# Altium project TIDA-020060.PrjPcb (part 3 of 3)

## Sheet Automotive_PoDL_PSE_Adapter_Hardware.SchDoc
size 431 x 279 mm; Date: Not shown in title block; ApprovedBy: Not shown in title block; CheckedBy: Not shown in title block; Author: Not shown in title block; CompanyName: Not shown in title block; Engineer: Not shown in title block; Organization: Not shown in title block; Address1: Not shown in title block; Address2: Not shown in title block; Address3: Not shown in title block; Address4: Not shown in title block; DocumentNumber: 3; Revision: Use project parameter SCH_Rev; SheetNumber: 19; SheetTotal: 19; PageSetup: Record=PageOptions¦CenterHorizontal=True¦CenterVertical=True¦PrintScale=1.00¦XCorrection=1.00¦YCorrection=1.00¦PrintKind=0¦BorderSize=5000000¦LeftOffset=0¦BottomOffset=0¦Orientation=2¦PaperLength=1000¦PaperWidth=1000¦Scale=100¦PaperSource=15¦PrintQuality=600¦MediaType=1¦DitherType=10¦PaperKind=Letter¦PrintScaleMode=1
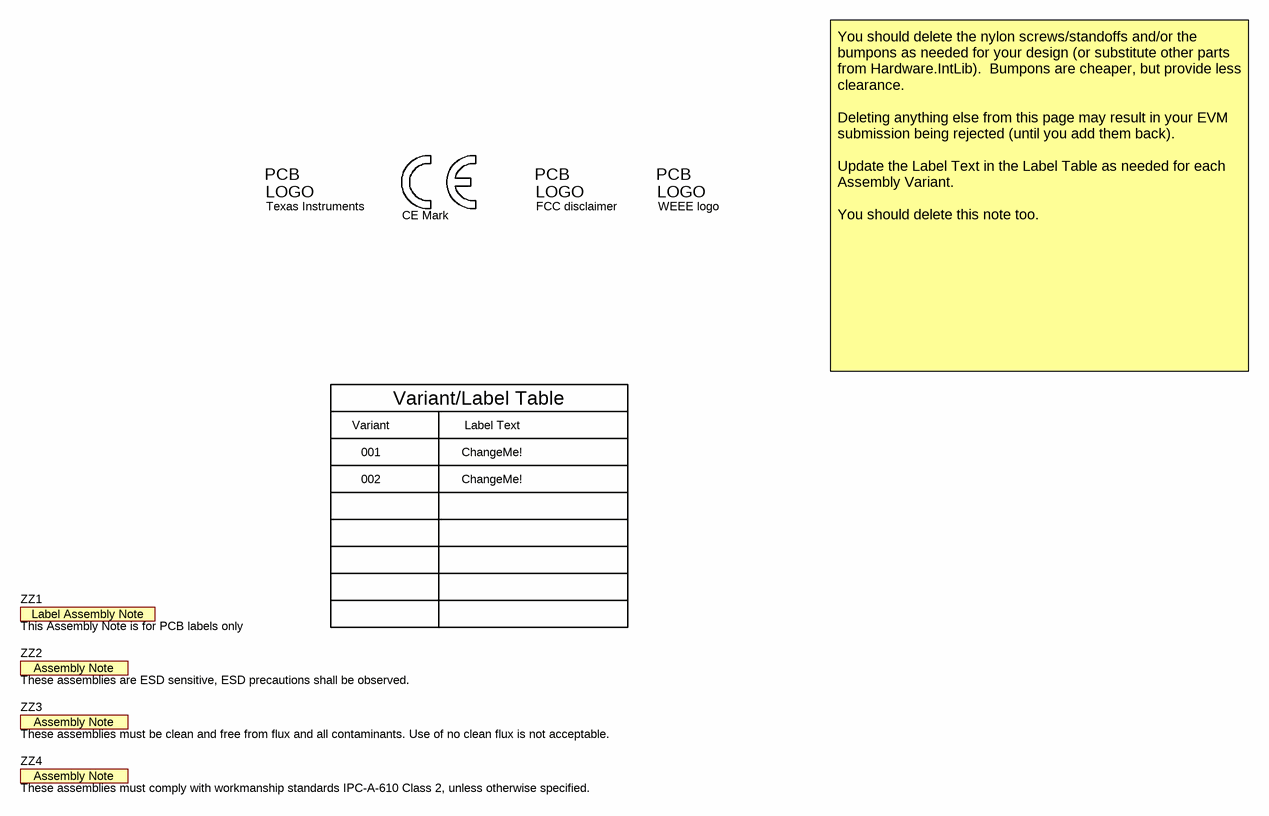
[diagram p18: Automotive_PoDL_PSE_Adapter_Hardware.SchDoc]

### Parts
Logo1  Texas Instruments  [TI_Stacked_Overlay_Small]  (no BOM)
Logo2  CE Mark  [CE_Mark_5mm]  (no BOM)
Logo3  FCC disclaimer  [FCC_disclaimer]  (no BOM)
Logo4  WEEE logo  [WEEE_Minimum]  (no BOM)
ZZ1  This Assembly Note is for PCB labels only  [AssemblyNoteLabel]  (no BOM)
ZZ2  These assemblies are ESD sensitive, ESD precautions shall be observed.  [AssemblyNote]  (no BOM)
ZZ3  These assemblies must be clean and free from flux and all contaminants. Use of no clean flux is not acceptable.  [AssemblyNote]  (no BOM)
ZZ4  These assemblies must comply with workmanship standards IPC-A-610 Class 2, unless otherwise specified.  [AssemblyNote]  (no BOM)

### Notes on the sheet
- Variant
- Variant/Label Table
- Label Text
- You should delete the nylon screws/standoffs and/or the bumpons as needed for your design (or substitute other parts from Hardware.IntLib).  Bumpons are cheaper, but provide less clearance.
  Deleting anything else from this page may result in your EVM submission being rejected (until you add them back).
  Update the Label Text in the Label Table as needed for each Assembly Variant.
  You should delete this note too.
- 001
- 002
- ChangeMe!

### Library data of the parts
Logo1 = CMP-0074838-1: Texas Instrument Corporate Signature; SymbolCreator: a0412235; Lib Reference: TI_Logo; Library Reference: Logo
Logo2 = CMP-0074844-1: SymbolCreator: a0412235
Logo3 = CMP-0074847-1: FCC_disclaimer; Library Reference: Logo
Logo4 = CMP-0074769-3: Manufacturer: Texas Instruments; AEC Category: Q200; CompType: IC
ZZ1 = CMP-0003616-3
ZZ2 = CMP-0077236-1
ZZ3 = CMP-0077237-1
ZZ4 = CMP-0077238-1

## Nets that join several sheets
+1V0: Power_caps (R72.1 R74.1), power_indicator_LEDs (R68.1), 1V0_LDO (L1.2 TP3.1)
+1V0_conn: Main (R16.2), 1V0_LDO (L1.1 R75.2)
+3V3: Main (8 pins), PHY (10 pins), Power_caps (6 pins), PHY_LED (R25.2 R26.2 R27.2 R28.2), 100Pin (J12.1), Board_ID_EEPROM (6 pins), power_indicator_LEDs (R93.1), 1V0_LDO (5 pins), PSE (J22.1), High_side_switch (C63.1 R113.1 R114.1 U11.4), Detection_PSE (7 pins), INA237 (C65.1 R104.1 R105.1 U12.6), GPIO_EXPANDER (5 pins)
+6V: power_indicator_LEDs (R66.2), Detection_PSE (6 pins)
+12V: Main (R15.1), power_indicator_LEDs (R1.2 R33.2 R61.2), PSE (J20.3 J21.3), Detection_PSE (C49.1 U5.5 U5.8)
GND: Main (R41.2 R60.2), PHY (17 pins), Power_caps (23 pins), PHY_LED (D7.1 D8.1), MDI (9 pins), 100Pin (61 pins), 60Pin (20 pins), Board_ID_EEPROM (C5.1 U4.4), power_indicator_LEDs (D1.1 D15.1 Q1.2 Q3.2), 1V0_LDO (7 pins), PSE (D13.1 J14.1 R108.1 TP8.1), High_side_switch (9 pins), PSE_BOOST (15 pins), Detection_PSE (21 pins), INA237 (5 pins), GPIO_EXPANDER (C55.1 R92.1 U9.8)
!ALERT: Main (TP11.1), INA237 (U12.3)
+3.3V_conn: Main (R22.2), 100Pin (J2.6 J2.8), 60Pin (J3.55 J3.56)
+12V_conn: Main (R15.2), 100Pin (J2.2), 60Pin (J3.27 J3.28)
A0: 60Pin (J3.14), Board_ID_EEPROM (R23.1 U4.1)
A1: 60Pin (J3.15), Board_ID_EEPROM (R63.1 U4.2)
A2: 60Pin (J3.16), Board_ID_EEPROM (R64.1 U4.3)
AE_INH: Main (J19.1 R60.1), PHY (U1.10), 100Pin (J2.97), 60Pin (J3.47)
AE_INT_N: Main (J4.1 R32.2), PHY (U1.2), 100Pin (J2.100), 60Pin (J3.31)
AE_LED_0: PHY (U1.35), PHY_LED (J5.2)
AE_LED_1: PHY (U1.6), PHY_LED (J6.2)
AE_RESET_N: Main (R20.1), PHY (TP13.1 U1.3), 100Pin (J2.26), 60Pin (J3.45), GPIO_EXPANDER (U9.3)
AE_RX_CLK: PHY (R14.2 R59.2 U1.27), 100Pin (R54.2)
AE_RX_CTRL: PHY (R31.1 R67.2 U1.15), 100Pin (R53.2)
AE_RX_D0: PHY (R3.2 U1.26), 100Pin (R55.2)
AE_RX_D1: PHY (R4.2 U1.25), 100Pin (R56.2)
AE_RX_N: PHY (U1.23), 100Pin (R58.2), SGMII_caps (R39.2)
AE_RX_P: PHY (R5.2 U1.24), 100Pin (R57.2), SGMII_caps (R40.2)
AE_TX_CLK: PHY (U1.28), 100Pin (R51.2)
AE_TX_CTRL: PHY (U1.29), 100Pin (R52.2)
AE_TX_D2: PHY (U1.31), 100Pin (R48.2)
AE_TX_D3: PHY (U1.30), 100Pin (R47.2)
AE_TX_N: PHY (U1.33), 100Pin (R50.2), SGMII_caps (R46.2)
AE_TX_P: PHY (U1.32), 100Pin (R49.2), SGMII_caps (R45.2)
AE_WAKE: Main (J11.2), PHY (U1.8), 100Pin (J2.98), 60Pin (J3.30)
comp_out: Detection_PSE (R86.1 U7.1 U7.6 U8.5), GPIO_EXPANDER (U9.10)
DUT_VDD1P0: Main (R16.1), 100Pin (J2.12)
EN: PSE (J22.2), High_side_switch (R112.1)
EN_detection: PSE (J17.2), Detection_PSE (Q5.1)
EN_detection_SoC: PSE (J17.1), GPIO_EXPANDER (U9.9)
EN_P17: PHY (U1.17), Power_caps (R62.2)
High_side_sw_VIN: PSE (J20.2), High_side_switch (5 pins)
HSS_EN: PSE (J23.1), GPIO_EXPANDER (U9.4)
HSS_FAULT: High_side_switch (U13.4), GPIO_EXPANDER (U9.7)
HSS_SNS: Main (R70.1), High_side_switch (U11.3), GPIO_EXPANDER (U9.6)
MDC: PHY (J7.1 J7.2), 100Pin (J2.20), 60Pin (J3.42)
MDIO: PHY (J7.4 J7.5), 100Pin (J2.22), 60Pin (J3.43)
PoDL_D+: MDI (L2.2 L5.3 L6.2 L12.3), PSE (R109.2), High_side_switch (U13.8 U13.9 U13.10), Detection_PSE (J15.2 R82.2 R83.2), INA237 (U12.8)
PoDL_D-: MDI (FB1.2 L2.3 L5.4 L12.2), PSE (R108.2 TP9.1), INA237 (U12.10)
PSE_boost_out: PSE (J18.1 TP10.1), PSE_BOOST (5 pins)
PSE_BOOST_VIN: PSE (J21.2), PSE_BOOST (5 pins)
Q: Main (R42.1), PSE (J22.3), Detection_PSE (R85.1 U8.6 U8.10), GPIO_EXPANDER (U9.5)
Q_N: PSE (J17.3), Detection_PSE (R84.1 U8.4 U8.8)
SCL: Main (R97.1), 100Pin (J2.30), 60Pin (J3.24), INA237 (U12.5), GPIO_EXPANDER (U9.14)
SDA: Main (R98.1), 100Pin (J2.28), 60Pin (J3.25), INA237 (U12.4), GPIO_EXPANDER (U9.15)
SGMII_2_RX_N: 100Pin (J2.88), 60Pin (J3.37), SGMII_caps (C33.1)
SGMII_2_RX_P: 100Pin (J2.86), 60Pin (J3.36), SGMII_caps (C34.1)
SGMII_2_TX_N: 100Pin (J2.94), 60Pin (J3.34), SGMII_caps (C36.1)
SGMII_2_TX_P: 100Pin (J2.92), 60Pin (J3.33), SGMII_caps (C1.1)
TRD_N: PHY (U1.13), MDI (C21.1 R9.1)
TRD_P: PHY (U1.12), MDI (C9.2 R8.1)
VDD1P0_P9: PHY (U1.9), Power_caps (5 pins)
VDD1P0_P21: PHY (U1.21), Power_caps (5 pins)
VDDA3P3_P11: PHY (U1.11), Power_caps (5 pins)
VDDIO_P22: PHY (U1.22), Power_caps (5 pins)
VDDIO_P34: PHY (U1.34), Power_caps (5 pins)
WKUP_I2C0_SCL: 60Pin (J3.21), Board_ID_EEPROM (U4.6)
WKUP_I2C0_SDA: 60Pin (J3.22), Board_ID_EEPROM (U4.5)
WP: 60Pin (J3.18), Board_ID_EEPROM (R65.1 U4.7)

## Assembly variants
STD: not fitted C7 C9 C21 C27 C48 C49 C50 C51 C52 C53 C54 C63 C64 C66 C69 D4 D11 D15 FB1 J15 J17 L5 L6 L7 L12 Q2 Q5 R3 R4 R5 R6 R7 R10 R14 R16 R22 R23 R23 R24 R35 R49 R50 R57 R58 R59 R63 R63 R66 R67 R76 R77 R78 R79 R80 R82 R83 R84 R85 R86 R87 R88 R89 R92 R97 R98 R100 R104 R105 U5 U6 U7 U8 U11 Y2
